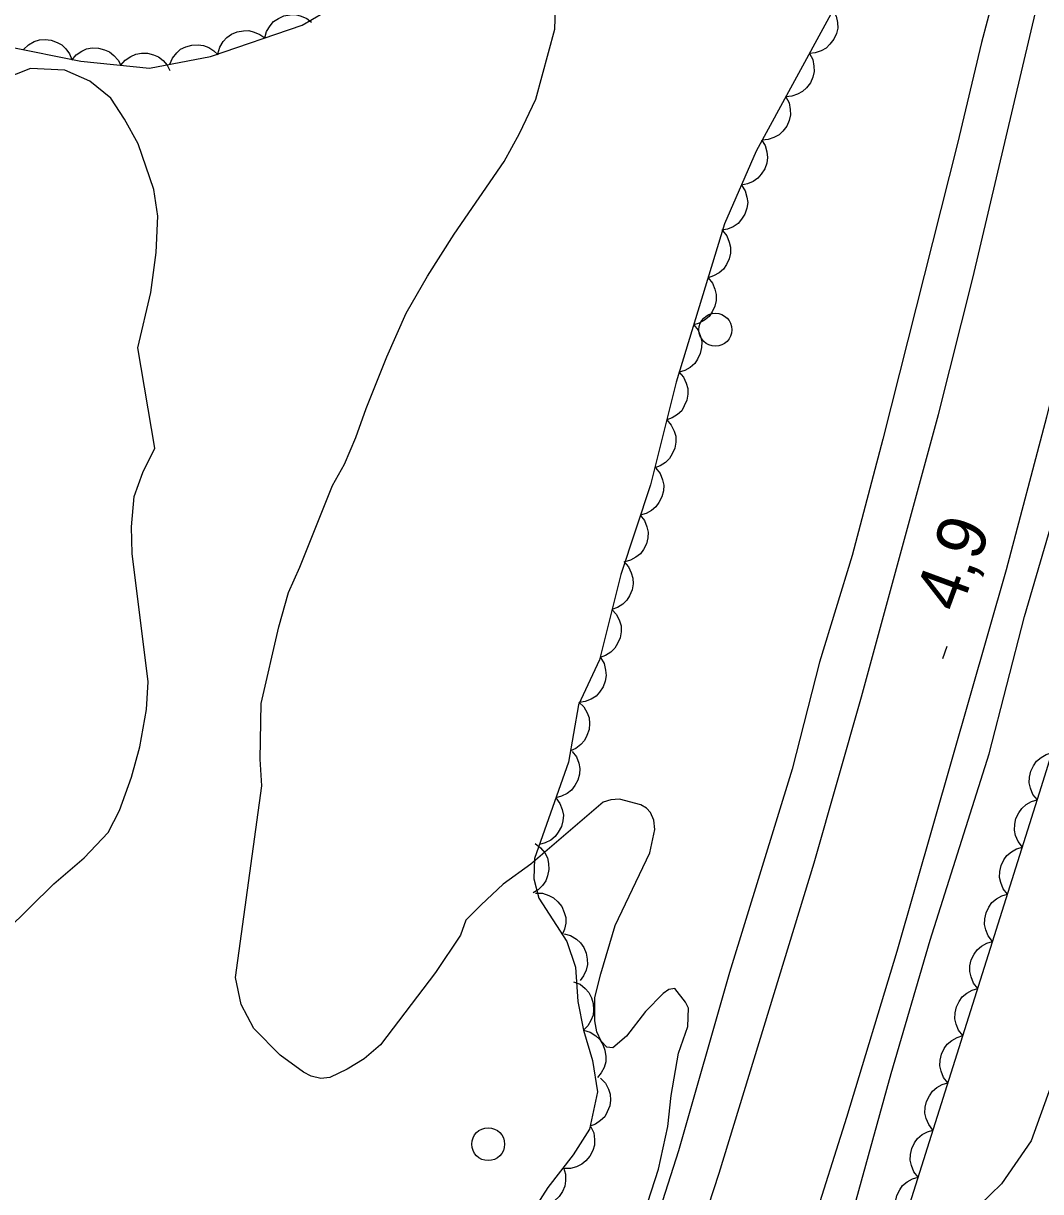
# Model space of a CAD drawing. Extents: x 282461 to 284471, y 5554090 to 5557646.
# Drawn here: x 283394.3 to 283456, y 5555625.8 to 5555696.7 of the extents above; entities that cross this region are included whole.
import ezdxf

# ---------------------------------------------------------------- set-up
doc = ezdxf.new("R2010")
doc.units = 0
for name, color, linetype in [('Niveau 2', 7, 'Continuous'), ('Niveau 21', 7, 'Continuous'), ('Niveau 3', 7, 'Continuous'), ('Niveau 36', 7, 'Continuous'), ('Niveau 44', 7, 'Continuous')]:
    doc.layers.add(name, color=color, linetype=linetype)

msp = doc.modelspace()

# ---------------------------------------------------------------- linework, layer by layer
at = {"layer": 'Niveau 2'}
for points in [[(283420.8, 5555641.39), (283419.28, 5555639.12), (283415.94, 5555634.73), (283414.96, 5555633.88), (283413.93, 5555633.26), (283412.88, 5555632.75), (283412.32, 5555632.68), (283411.75, 5555632.83), (283411.28, 5555633.08), (283409.86, 5555634.11), (283408.27, 5555635.73), (283407.49, 5555637.19), (283407.15, 5555638.83), (283408.75, 5555650.46), (283408.65, 5555652.07), (283408.7, 5555655.45), (283409.77, 5555660.1), (283410.36, 5555662.2), (283411.06, 5555663.74), (283413.03, 5555668.69), (283413.77, 5555669.98), (283414.46, 5555671.6), (283415.08, 5555673.37), (283416.34, 5555676.51), (283417.51, 5555679.16), (283418.8, 5555681.4), (283420.43, 5555683.94), (283423.46, 5555688.36), (283424.39, 5555690.05), (283425.37, 5555692.15), (283426.53, 5555696.39), (283426.59, 5555698.27)], [(283477.44, 5555695.69), (283476.19, 5555692.13), (283474.3, 5555688.64), (283472.65, 5555686.86), (283471.88, 5555685.25), (283471.64, 5555683.75), (283471.19, 5555681.95), (283470.81, 5555679.43), (283469.73, 5555676.87), (283467.09, 5555667.68), (283464.76, 5555663.61), (283464.43, 5555661.43), (283461.96, 5555653.08), (283460.01, 5555648.6), (283458.89, 5555646.88), (283457.71, 5555643.63), (283457.11, 5555637.58), (283457.34, 5555636.68), (283456.61, 5555632.17), (283455.45, 5555628.91), (283453.65, 5555626.3), (283451.64, 5555624.36)], [(283391.73, 5555640.19), (283396.12, 5555644.51), (283397.96, 5555646.08), (283399.42, 5555647.62), (283400.11, 5555648.95), (283400.84, 5555650.99), (283401.34, 5555652.82), (283401.75, 5555655.09), (283401.84, 5555656.76), (283400.87, 5555664.57), (283400.83, 5555666.18), (283401, 5555668.02), (283401.53, 5555669.48), (283402.26, 5555670.95), (283401.23, 5555677.05), (283402.02, 5555680.41), (283402.34, 5555682.84), (283402.44, 5555685.04), (283402.19, 5555686.66), (283401.24, 5555689.43), (283400.41, 5555690.93), (283399.59, 5555692.2), (283398.3, 5555693.23), (283396.79, 5555693.91), (283394.7, 5555694.01), (283392.96, 5555693.31)], [(283431.95, 5555624.5), (283432.83, 5555627.18), (283433.38, 5555629.77), (283433.59, 5555631.65), (283434.03, 5555634.23), (283434.61, 5555635.85), (283434.64, 5555636.95), (283434.46, 5555637.33), (283433.81, 5555638.16), (283433.45, 5555638.09), (283433.11, 5555637.84), (283432.03, 5555636.75), (283430.88, 5555635.26), (283430.06, 5555634.56), (283429.68, 5555634.6), (283429.34, 5555634.96), (283429.09, 5555635.53), (283428.96, 5555636.19), (283428.95, 5555637.6), (283429.33, 5555639.04), (283430.2, 5555641.98), (283432.3, 5555646.39), (283432.59, 5555647.81), (283432.53, 5555648.38), (283432.34, 5555648.83), (283432.09, 5555649.11), (283431.76, 5555649.31), (283430.46, 5555649.65), (283429.93, 5555649.61), (283429.46, 5555649.46), (283425.07, 5555645.71), (283423.4, 5555644.49), (283422.05, 5555643.24), (283421.13, 5555642.3), (283420.8, 5555641.39)]]:
    msp.add_lwpolyline(points, dxfattribs=at)
at = {"layer": 'Niveau 21'}
for points in [[(283414.13, 5555540), (283418.84, 5555553.93), (283419.91, 5555557.46), (283426.49, 5555576.38), (283428.12, 5555581.53), (283434.29, 5555599.3), (283436.32, 5555605.56), (283438.12, 5555611.58), (283442.13, 5555623.62), (283444.25, 5555630.34), (283447.3, 5555640.42), (283453.95, 5555663.59), (283456.39, 5555672.85), (283459.42, 5555684.95), (283464.49, 5555706.31), (283467.84, 5555721.65), (283469.14, 5555728.42), (283472.32, 5555743.35)], [(283415.8, 5555538.57), (283420.56, 5555553.08), (283423.11, 5555560.03), (283428.7, 5555576.41), (283431.25, 5555583.36), (283433.23, 5555589.44), (283436.37, 5555598.42), (283442.18, 5555617.12), (283444.72, 5555624.94), (283446.95, 5555632.99), (283449.31, 5555641.09), (283452.9, 5555652.39), (283455.03, 5555660.73), (283460.13, 5555678.16), (283462.15, 5555686.38), (283464.34, 5555694.72), (283467, 5555705.95), (283469.69, 5555720.07), (283473.73, 5555739.57)], [(283462.47, 5555738.31), (283461.2, 5555731.43), (283459.1, 5555721.82), (283455.87, 5555709.31), (283454.14, 5555702.08), (283452.42, 5555695.59), (283450.97, 5555689.45), (283446.43, 5555671.5), (283444.57, 5555664.44), (283442.6, 5555657.96), (283440.94, 5555651.47), (283437.13, 5555639.13), (283434.03, 5555628.3), (283430.28, 5555616.54), (283429.1, 5555612.08), (283426.86, 5555604.89), (283422.22, 5555591.86), (283420.36, 5555585.73), (283418.72, 5555580.92), (283417.08, 5555576.81), (283412, 5555561.47), (283405.35, 5555543.77), (283400.81, 5555527.66)], [(283406.23, 5555536.33), (283411.71, 5555552.99), (283429.04, 5555604.08), (283436.5, 5555626.95), (283442.28, 5555645.78), (283445.15, 5555655.85), (283449.82, 5555673), (283451.9, 5555681.28), (283458.81, 5555710.63), (283460.71, 5555718.97), (283464.36, 5555736.1)]]:
    msp.add_lwpolyline(points, dxfattribs=at)
at = {"layer": 'Niveau 3'}
msp.add_line((283450.07, 5555658.18), (283450.35, 5555658.93), dxfattribs=at)
at = {"layer": 'Niveau 36'}
for centre in [(283436.274, 5555678.146), (283422.486, 5555628.701)]:
    msp.add_circle(centre, 1, dxfattribs=at)
at = {"layer": 'Niveau 44'}
for points in [[(283447.36, 5555622.84), (283456.07, 5555650.42), (283463.07, 5555672.9), (283464.19, 5555677.53), (283466.22, 5555684.02), (283467.36, 5555686.34), (283468.97, 5555688.2), (283469.88, 5555690.06), (283470.08, 5555693.53), (283469.8, 5555699.31), (283471.35, 5555707.87), (283472.47, 5555713.2), (283473.82, 5555718.07), (283475.65, 5555720.4), (283477.03, 5555722.72), (283477.69, 5555726.19), (283476.96, 5555730.35), (283476.91, 5555736.6)], [(283445.49, 5555701.38), (283438.76, 5555688.98), (283436.83, 5555684.58), (283433.9, 5555674.97), (283432.33, 5555668.73), (283430.53, 5555663.29), (283429.24, 5555658.1), (283427.96, 5555655.38), (283427.36, 5555651.89), (283425.3, 5555646.05), (283425.25, 5555644.8), (283425.55, 5555643.64), (283427.25, 5555641), (283427.79, 5555639.44), (283427.92, 5555637.36), (283428.28, 5555635.63), (283428.82, 5555633.78), (283429.13, 5555631.88), (283428.63, 5555629.62), (283427.65, 5555628.05), (283426.1, 5555626.08), (283424.85, 5555624.11)], [(283393.34, 5555695.35), (283397.76, 5555694.45), (283401.94, 5555694.02), (283405.64, 5555694.74), (283411.19, 5555696.63), (283415.58, 5555699.21)], [(283408.92, 5555695.86), (283409.03, 5555696.26), (283409.25, 5555696.6), (283409.46, 5555696.86), (283409.75, 5555697.05), (283410.09, 5555697.2), (283410.47, 5555697.26), (283410.79, 5555697.28), (283411.13, 5555697.19), (283411.47, 5555697.04), (283411.76, 5555696.82)], [(283443.41, 5555697.56), (283443.61, 5555697.19), (283443.68, 5555696.79), (283443.7, 5555696.46), (283443.62, 5555696.12), (283443.47, 5555695.78), (283443.23, 5555695.48), (283443, 5555695.24), (283442.69, 5555695.08), (283442.34, 5555694.96), (283441.98, 5555694.92)], [(283394.28, 5555695.16), (283394.58, 5555695.45), (283394.94, 5555695.64), (283395.25, 5555695.75), (283395.6, 5555695.77), (283395.96, 5555695.73), (283396.32, 5555695.59), (283396.61, 5555695.44), (283396.86, 5555695.19), (283397.08, 5555694.89), (283397.22, 5555694.56)], [(283406.08, 5555694.89), (283406.19, 5555695.29), (283406.41, 5555695.64), (283406.62, 5555695.89), (283406.91, 5555696.09), (283407.25, 5555696.23), (283407.63, 5555696.3), (283407.95, 5555696.31), (283408.29, 5555696.22), (283408.63, 5555696.07), (283408.92, 5555695.86)], [(283397.21, 5555694.51), (283397.47, 5555694.83), (283397.82, 5555695.05), (283398.11, 5555695.19), (283398.46, 5555695.25), (283398.83, 5555695.24), (283399.2, 5555695.14), (283399.5, 5555695.02), (283399.77, 5555694.8), (283400.02, 5555694.52), (283400.19, 5555694.2)], [(283403.16, 5555694.26), (283403.32, 5555694.64), (283403.58, 5555694.95), (283403.82, 5555695.17), (283404.14, 5555695.33), (283404.49, 5555695.43), (283404.88, 5555695.44), (283405.2, 5555695.41), (283405.53, 5555695.28), (283405.84, 5555695.08), (283406.1, 5555694.83)], [(283400.19, 5555694.2), (283400.46, 5555694.52), (283400.8, 5555694.74), (283401.1, 5555694.88), (283401.44, 5555694.94), (283401.81, 5555694.93), (283402.18, 5555694.83), (283402.48, 5555694.71), (283402.76, 5555694.49), (283403, 5555694.21), (283403.17, 5555693.89)], [(283441.98, 5555694.92), (283442.18, 5555694.55), (283442.25, 5555694.15), (283442.27, 5555693.82), (283442.18, 5555693.48), (283442.04, 5555693.14), (283441.8, 5555692.84), (283441.57, 5555692.61), (283441.26, 5555692.44), (283440.91, 5555692.32), (283440.55, 5555692.29)], [(283440.55, 5555692.29), (283440.75, 5555691.92), (283440.82, 5555691.52), (283440.84, 5555691.19), (283440.75, 5555690.85), (283440.61, 5555690.51), (283440.37, 5555690.21), (283440.14, 5555689.97), (283439.83, 5555689.81), (283439.48, 5555689.69), (283439.12, 5555689.65)], [(283439.07, 5555689.68), (283439.29, 5555689.33), (283439.4, 5555688.94), (283439.44, 5555688.61), (283439.39, 5555688.26), (283439.27, 5555687.91), (283439.06, 5555687.59), (283438.85, 5555687.34), (283438.56, 5555687.15), (283438.22, 5555687), (283437.86, 5555686.93)], [(283437.86, 5555686.93), (283438.09, 5555686.58), (283438.19, 5555686.19), (283438.24, 5555685.86), (283438.18, 5555685.52), (283438.06, 5555685.17), (283437.85, 5555684.85), (283437.65, 5555684.59), (283437.35, 5555684.4), (283437.01, 5555684.25), (283436.66, 5555684.19)], [(283436.71, 5555684.17), (283436.97, 5555683.85), (283437.12, 5555683.47), (283437.2, 5555683.15), (283437.19, 5555682.8), (283437.11, 5555682.44), (283436.94, 5555682.1), (283436.77, 5555681.82), (283436.5, 5555681.6), (283436.17, 5555681.41), (283435.83, 5555681.3)], [(283435.83, 5555681.3), (283436.09, 5555680.98), (283436.25, 5555680.6), (283436.33, 5555680.28), (283436.32, 5555679.93), (283436.24, 5555679.57), (283436.07, 5555679.23), (283435.89, 5555678.95), (283435.62, 5555678.73), (283435.3, 5555678.54), (283434.96, 5555678.44)], [(283434.96, 5555678.44), (283435.22, 5555678.11), (283435.37, 5555677.74), (283435.45, 5555677.42), (283435.44, 5555677.06), (283435.36, 5555676.7), (283435.19, 5555676.36), (283435.02, 5555676.09), (283434.75, 5555675.86), (283434.43, 5555675.68), (283434.08, 5555675.57)], [(283434.05, 5555675.58), (283434.33, 5555675.27), (283434.5, 5555674.9), (283434.6, 5555674.58), (283434.6, 5555674.23), (283434.55, 5555673.87), (283434.39, 5555673.52), (283434.23, 5555673.23), (283433.97, 5555673), (283433.66, 5555672.79), (283433.32, 5555672.67)], [(283433.32, 5555672.67), (283433.6, 5555672.36), (283433.77, 5555671.99), (283433.87, 5555671.68), (283433.87, 5555671.32), (283433.81, 5555670.96), (283433.66, 5555670.61), (283433.5, 5555670.33), (283433.24, 5555670.09), (283432.93, 5555669.89), (283432.59, 5555669.76)], [(283432.66, 5555669.74), (283432.92, 5555669.41), (283433.06, 5555669.03), (283433.14, 5555668.71), (283433.12, 5555668.36), (283433.03, 5555668), (283432.85, 5555667.66), (283432.67, 5555667.39), (283432.39, 5555667.17), (283432.07, 5555666.99), (283431.72, 5555666.89)], [(283431.72, 5555666.89), (283431.98, 5555666.56), (283432.12, 5555666.18), (283432.2, 5555665.86), (283432.17, 5555665.51), (283432.09, 5555665.15), (283431.91, 5555664.81), (283431.73, 5555664.54), (283431.45, 5555664.33), (283431.13, 5555664.15), (283430.78, 5555664.05)], [(283430.72, 5555664.07), (283431, 5555663.76), (283431.17, 5555663.39), (283431.27, 5555663.07), (283431.28, 5555662.72), (283431.22, 5555662.36), (283431.07, 5555662), (283430.91, 5555661.72), (283430.65, 5555661.48), (283430.34, 5555661.28), (283430, 5555661.16)], [(283430, 5555661.16), (283430.28, 5555660.85), (283430.45, 5555660.48), (283430.55, 5555660.16), (283430.56, 5555659.81), (283430.5, 5555659.45), (283430.34, 5555659.1), (283430.18, 5555658.81), (283429.92, 5555658.57), (283429.61, 5555658.37), (283429.28, 5555658.25)], [(283429.3, 5555658.24), (283429.52, 5555657.88), (283429.61, 5555657.48), (283429.65, 5555657.16), (283429.59, 5555656.81), (283429.46, 5555656.46), (283429.24, 5555656.15), (283429.03, 5555655.9), (283428.73, 5555655.72), (283428.38, 5555655.58), (283428.03, 5555655.52)], [(283427.99, 5555655.54), (283428.29, 5555655.25), (283428.49, 5555654.89), (283428.61, 5555654.59), (283428.64, 5555654.24), (283428.61, 5555653.87), (283428.48, 5555653.51), (283428.34, 5555653.21), (283428.1, 5555652.96), (283427.81, 5555652.73), (283427.48, 5555652.58)], [(283427.59, 5555652.55), (283427.84, 5555652.22), (283427.98, 5555651.83), (283428.05, 5555651.51), (283428.02, 5555651.16), (283427.93, 5555650.8), (283427.74, 5555650.47), (283427.55, 5555650.2), (283427.27, 5555649.99), (283426.94, 5555649.82), (283426.6, 5555649.73)], [(283455.82, 5555649.6), (283455.55, 5555649.93), (283455.4, 5555650.31), (283455.32, 5555650.63), (283455.34, 5555650.98), (283455.42, 5555651.34), (283455.59, 5555651.68), (283455.77, 5555651.96), (283456.04, 5555652.18), (283456.36, 5555652.36), (283456.71, 5555652.47)], [(283426.6, 5555649.73), (283426.84, 5555649.39), (283426.98, 5555649.01), (283427.05, 5555648.68), (283427.02, 5555648.33), (283426.93, 5555647.98), (283426.74, 5555647.64), (283426.56, 5555647.37), (283426.28, 5555647.16), (283425.95, 5555646.99), (283425.6, 5555646.9)], [(283454.91, 5555646.74), (283454.65, 5555647.07), (283454.5, 5555647.45), (283454.42, 5555647.77), (283454.44, 5555648.12), (283454.52, 5555648.48), (283454.69, 5555648.82), (283454.87, 5555649.09), (283455.14, 5555649.32), (283455.47, 5555649.5), (283455.81, 5555649.6)], [(283425.34, 5555646.95), (283425.67, 5555646.7), (283425.92, 5555646.38), (283426.08, 5555646.09), (283426.15, 5555645.74), (283426.17, 5555645.38), (283426.09, 5555645), (283425.99, 5555644.69), (283425.78, 5555644.4), (283425.52, 5555644.14), (283425.22, 5555643.95)], [(283454, 5555643.88), (283453.74, 5555644.2), (283453.59, 5555644.58), (283453.52, 5555644.9), (283453.53, 5555645.26), (283453.61, 5555645.62), (283453.79, 5555645.96), (283453.97, 5555646.23), (283454.24, 5555646.45), (283454.56, 5555646.64), (283454.91, 5555646.74)], [(283425.36, 5555643.93), (283425.78, 5555643.93), (283426.16, 5555643.8), (283426.46, 5555643.65), (283426.72, 5555643.42), (283426.95, 5555643.13), (283427.1, 5555642.77), (283427.19, 5555642.46), (283427.19, 5555642.11), (283427.12, 5555641.75), (283426.98, 5555641.41)], [(283453.1, 5555641.01), (283452.84, 5555641.34), (283452.69, 5555641.72), (283452.61, 5555642.04), (283452.63, 5555642.39), (283452.71, 5555642.75), (283452.88, 5555643.09), (283453.06, 5555643.37), (283453.34, 5555643.59), (283453.66, 5555643.77), (283454, 5555643.88)], [(283427.09, 5555641.47), (283427.49, 5555641.36), (283427.84, 5555641.14), (283428.09, 5555640.93), (283428.29, 5555640.64), (283428.44, 5555640.3), (283428.5, 5555639.93), (283428.52, 5555639.6), (283428.43, 5555639.26), (283428.28, 5555638.92), (283428.07, 5555638.63)], [(283452.2, 5555638.15), (283451.94, 5555638.48), (283451.79, 5555638.86), (283451.71, 5555639.18), (283451.72, 5555639.53), (283451.8, 5555639.89), (283451.98, 5555640.23), (283452.16, 5555640.5), (283452.43, 5555640.73), (283452.75, 5555640.91), (283453.1, 5555641.01)], [(283427.67, 5555638.56), (283428.06, 5555638.41), (283428.37, 5555638.15), (283428.6, 5555637.91), (283428.75, 5555637.59), (283428.86, 5555637.24), (283428.87, 5555636.86), (283428.85, 5555636.53), (283428.72, 5555636.2), (283428.53, 5555635.89), (283428.28, 5555635.63)], [(283451.29, 5555635.29), (283451.03, 5555635.62), (283450.88, 5555635.99), (283450.8, 5555636.31), (283450.82, 5555636.67), (283450.9, 5555637.03), (283451.08, 5555637.37), (283451.25, 5555637.64), (283451.53, 5555637.86), (283451.85, 5555638.05), (283452.2, 5555638.15)], [(283428.28, 5555635.63), (283428.68, 5555635.5), (283429.01, 5555635.27), (283429.26, 5555635.05), (283429.44, 5555634.75), (283429.57, 5555634.4), (283429.62, 5555634.02), (283429.62, 5555633.7), (283429.52, 5555633.36), (283429.35, 5555633.03), (283429.12, 5555632.75)], [(283450.39, 5555632.42), (283450.13, 5555632.75), (283449.98, 5555633.13), (283449.9, 5555633.45), (283449.92, 5555633.8), (283450, 5555634.16), (283450.17, 5555634.51), (283450.35, 5555634.78), (283450.62, 5555635), (283450.95, 5555635.18), (283451.29, 5555635.29)], [(283429.31, 5555632.71), (283429.6, 5555632.41), (283429.78, 5555632.05), (283429.89, 5555631.73), (283429.9, 5555631.38), (283429.86, 5555631.02), (283429.71, 5555630.66), (283429.56, 5555630.37), (283429.31, 5555630.13), (283429, 5555629.92), (283428.67, 5555629.79)], [(283449.48, 5555629.56), (283449.22, 5555629.89), (283449.07, 5555630.27), (283448.99, 5555630.59), (283449.01, 5555630.94), (283449.09, 5555631.3), (283449.27, 5555631.64), (283449.45, 5555631.92), (283449.72, 5555632.14), (283450.04, 5555632.32), (283450.39, 5555632.42)], [(283428.72, 5555629.76), (283428.89, 5555629.38), (283428.94, 5555628.98), (283428.94, 5555628.65), (283428.83, 5555628.31), (283428.66, 5555627.98), (283428.41, 5555627.7), (283428.17, 5555627.48), (283427.85, 5555627.33), (283427.49, 5555627.23), (283427.13, 5555627.22)], [(283448.58, 5555626.7), (283448.32, 5555627.03), (283448.17, 5555627.41), (283448.09, 5555627.73), (283448.11, 5555628.08), (283448.19, 5555628.44), (283448.36, 5555628.78), (283448.54, 5555629.05), (283448.82, 5555629.28), (283449.14, 5555629.46), (283449.48, 5555629.56)], [(283427.05, 5555627.28), (283427.17, 5555626.88), (283427.18, 5555626.48), (283427.14, 5555626.15), (283427, 5555625.83), (283426.8, 5555625.52), (283426.51, 5555625.26), (283426.25, 5555625.07), (283425.92, 5555624.96), (283425.55, 5555624.9), (283425.19, 5555624.93)], [(283447.67, 5555623.84), (283447.41, 5555624.16), (283447.27, 5555624.54), (283447.19, 5555624.86), (283447.2, 5555625.21), (283447.28, 5555625.58), (283447.46, 5555625.92), (283447.64, 5555626.19), (283447.91, 5555626.41), (283448.23, 5555626.6), (283448.58, 5555626.7)]]:
    msp.add_lwpolyline(points, dxfattribs=at)

# ---------------------------------------------------------------- texts
at = {"layer": 'Niveau 3'}
msp.add_text('4,9  ', height=3, rotation=69.87477, dxfattribs=at).set_placement((283451.1, 5555660.87))

doc.saveas('drawing.dxf')
